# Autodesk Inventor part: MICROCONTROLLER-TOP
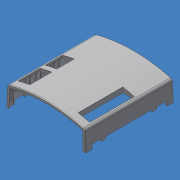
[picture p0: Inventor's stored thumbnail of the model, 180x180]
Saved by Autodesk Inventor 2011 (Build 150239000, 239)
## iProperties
Created: 2007-09
Part Number: MICROCONTROLLER-TOP
Document SubType Name: Modeling
Density: 1 g/cm^3
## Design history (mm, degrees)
feature "Base1"
body "Solid1"
